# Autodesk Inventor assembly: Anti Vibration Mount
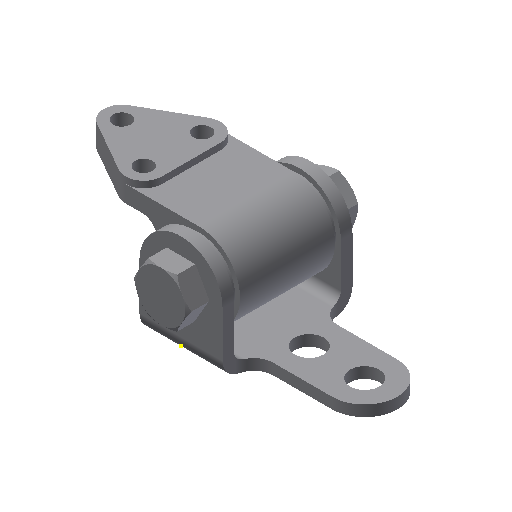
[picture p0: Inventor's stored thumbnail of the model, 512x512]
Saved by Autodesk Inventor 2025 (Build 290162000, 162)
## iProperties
Created: 2011-07
Part Number: Anti Vibration Mount
Document SubType Name: Assembly
Designer: CadCim
Author: CadCim
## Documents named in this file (5)
- D:\CAD\Inventor\Autodesk Inventor 2025\Resources\2025\c09_Inv_2025_tut\c09_tut03_inv\Anti Vibration Mount\Anti Vibration Mount.iam
- D:\CAD\Inventor\Autodesk Inventor 2025\Resources\2025\c09_Inv_2025_tut\c09_tut03_inv\Anti Vibration Mount\Yoke Plate.ipt
- D:\CAD\Inventor\Autodesk Inventor 2025\Resources\2025\c09_Inv_2025_tut\c09_tut03_inv\Anti Vibration Mount\Body-Bushing Ruber.iam
- D:\CAD\Inventor\Autodesk Inventor 2025\Resources\2025\c09_Inv_2025_tut\c09_tut03_inv\Anti Vibration Mount\Hex Bolt.ipt
- D:\CAD\Inventor\Autodesk Inventor 2025\Resources\2025\c09_Inv_2025_tut\c09_tut03_inv\Anti Vibration Mount\Nut.ipt
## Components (4 placed, 4 different names)
1. Yoke Plate:1 — Insert:1, Angle:1, Mate:1, Mate:2, Mate:3
2. Body-Bushing Ruber:1 [sub-assembly] — Insert:1, Angle:1
3. Hex Bolt:1 — Mate:2, Mate:3, Mate:4
4. Nut:1 — Mate:1, Mate:4
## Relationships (6: Mate 4, Insert 1, Angle 1)
- Insert:1: Yoke Plate:1 ↔ Body-Bushing Ruber:1
- Angle:1: Yoke Plate:1 ↔ Body-Bushing Ruber:1
- Mate:1: Yoke Plate:1 ↔ Nut:1
- Mate:2: Yoke Plate:1 ↔ Hex Bolt:1
- Mate:3: Yoke Plate:1 ↔ Hex Bolt:1
- Mate:4: Hex Bolt:1 ↔ Nut:1
